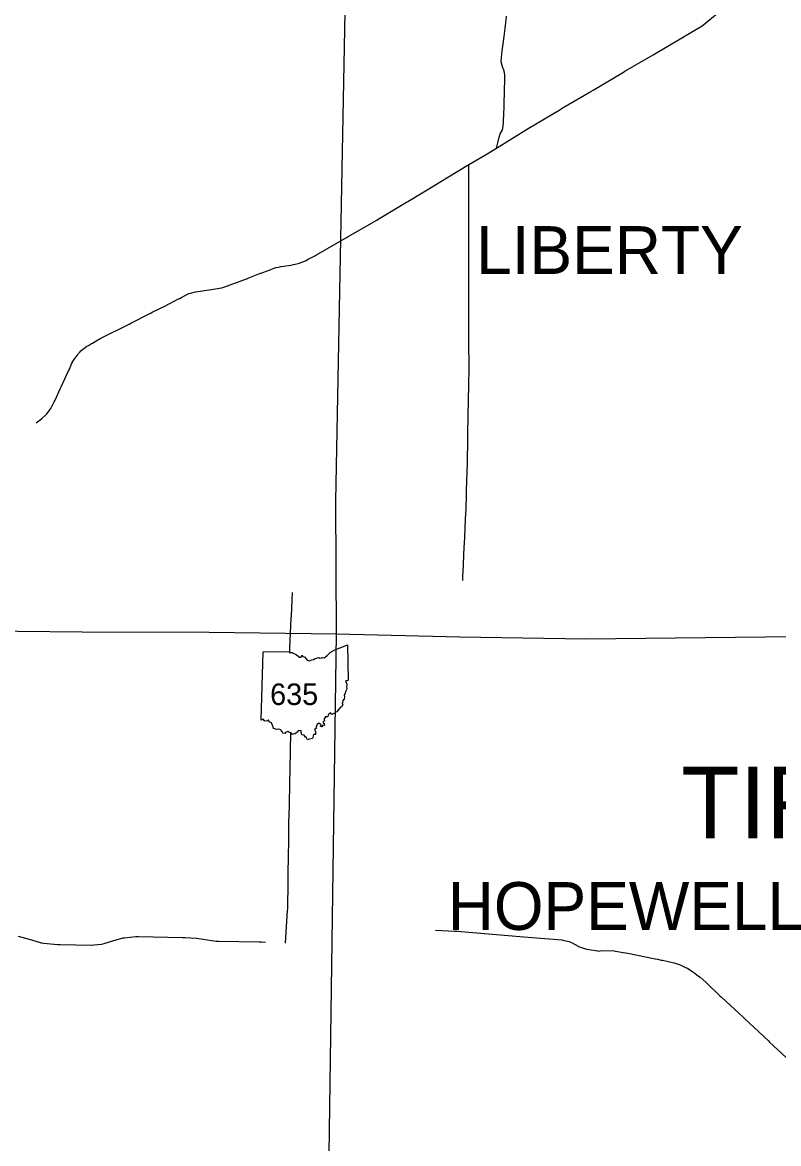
# Model space of a CAD drawing. Extents: x -232 to 448, y 619 to 1059.
# Drawn here: x 225.38 to 257.82, y 726.2 to 774.33 of the extents above; entities that cross this region are included whole.
import ezdxf

# ---------------------------------------------------------------- set-up
doc = ezdxf.new("R2010")
doc.units = 0
doc.layers.add('Default', color=7, linetype='Continuous')

msp = doc.modelspace()

# ---------------------------------------------------------------- linework, layer by layer
at = {"layer": 'Default'}
msp.add_line((235.625, 744.376), (235.707, 747.305), dxfattribs=at)
msp.add_line((235.625, 744.376), (235.707, 747.305), dxfattribs=at)
for points in [[(238.85, 748.082), (238.831, 753.779), (239.337, 780.795)], [(248.168, 770.427), (248.427, 770.582), (248.506, 770.629), (249.769, 771.367), (249.858, 771.419), (251.16, 772.198), (251.217, 772.232), (252.434, 772.942), (252.509, 772.986), (253.768, 773.731), (253.817, 773.76), (254.474, 774.14), (254.539, 774.177), (255.582, 775.042), (255.638, 775.087), (256.714, 775.996), (256.765, 776.038), (257.088, 776.311)], [(245.718, 768.939), (245.773, 769.158), (245.836, 769.407), (245.873, 769.554), (245.975, 769.713), (246.008, 769.882), (246.015, 770.067), (246.029, 770.419), (246.039, 770.672), (246.05, 770.975), (246.058, 771.228), (246.066, 771.513), (246.073, 771.782), (246.08, 772.07), (246.043, 772.254), (245.979, 772.43), (245.92, 772.644), (245.927, 772.821), (245.963, 773.108), (246, 773.41), (246.04, 773.731), (246.083, 774.068), (246.114, 774.317), (246.144, 774.603)], [(245.239, 768.653), (245.64, 768.892), (245.718, 768.939), (247.008, 769.736), (247.077, 769.779), (248.168, 770.427)], [(237.996, 764.352), (239.307, 765.116), (239.356, 765.144), (240.577, 765.847), (240.642, 765.885), (241.851, 766.608), (241.914, 766.646), (243.214, 767.427), (243.262, 767.456), (244.465, 768.189), (244.465, 768.189), (244.524, 768.225), (245.239, 768.653)], [(244.527, 764.31), (244.524, 765.662), (244.524, 765.728), (244.531, 766.758), (244.532, 766.853), (244.524, 768.153), (244.524, 768.153), (244.524, 768.225)], [(225.966, 757.137), (226.136, 757.264), (226.217, 757.325), (226.375, 757.473), (226.433, 757.528), (226.558, 757.705), (226.593, 757.754), (226.743, 758.043), (226.778, 758.11), (227.002, 758.603), (227.037, 758.68), (227.355, 759.368), (227.393, 759.449), (227.505, 759.696), (227.54, 759.774), (227.633, 759.908), (227.674, 759.967), (227.74, 760.053), (227.775, 760.099), (227.847, 760.18), (227.888, 760.227), (227.968, 760.299), (228.011, 760.338), (228.147, 760.427), (228.208, 760.467), (228.302, 760.522), (228.381, 760.568), (228.615, 760.705), (228.615, 760.705), (228.673, 760.739), (228.721, 760.763), (229.934, 761.365), (229.953, 761.374), (230.03, 761.414), (230.848, 761.838), (230.882, 761.855), (230.944, 761.886), (231.575, 762.199), (231.609, 762.215), (231.672, 762.248), (232.104, 762.473), (232.127, 762.485), (232.2, 762.523), (232.487, 762.675), (232.519, 762.693), (232.589, 762.71), (232.798, 762.765), (232.802, 762.766), (232.906, 762.78), (233.389, 762.844), (233.393, 762.845), (233.495, 762.863), (233.922, 762.937), (233.972, 762.946), (234.026, 762.965), (234.992, 763.321), (235.012, 763.328), (235.093, 763.36), (235.596, 763.559), (235.626, 763.571), (235.698, 763.598), (236.001, 763.713), (236.037, 763.727), (236.103, 763.75), (236.256, 763.804), (236.265, 763.807), (236.362, 763.828), (236.468, 763.852), (236.481, 763.855), (236.575, 763.866), (236.897, 763.907), (236.907, 763.908), (237.003, 763.932), (237.213, 763.984), (237.264, 763.997), (237.316, 764.017), (237.517, 764.098), (237.546, 764.11), (237.613, 764.146), (237.804, 764.249), (237.832, 764.264), (237.899, 764.3), (237.947, 764.326), (237.996, 764.352)], [(244.528, 763.223), (244.528, 763.929), (244.527, 764.31)], [(244.266, 750.367), (244.277, 750.61), (244.281, 750.702), (244.336, 751.838), (244.341, 751.938), (244.371, 752.587), (244.374, 752.648), (244.404, 753.297), (244.404, 753.297), (244.409, 753.388), (244.45, 754.796), (244.452, 754.879), (244.481, 756.287), (244.483, 756.364), (244.508, 757.718), (244.509, 757.816), (244.536, 759.062), (244.538, 759.167), (244.535, 760.955), (244.534, 761.06), (244.528, 762.36), (244.528, 762.431), (244.528, 763.223)], [(236.849, 747.323), (236.85, 747.361), (236.853, 747.466), (236.914, 748.765), (236.918, 748.848), (236.965, 749.851)], [(205.775, 748.382), (218.839, 748.24), (222.221, 748.221), (222.402, 748.227), (227.948, 748.176), (233.391, 748.153), (238.85, 748.082)], [(238.399, 715.587), (238.85, 748.082)], [(238.85, 748.082), (244.144, 747.953), (249.543, 747.875), (271.364, 748.108)], [(235.707, 747.305), (236.844, 747.324), (236.826, 747.289), (236.933, 747.282), (237.047, 747.219), (237.143, 747.179), (237.261, 747.086), (237.332, 747.087), (237.361, 747.164), (237.415, 747.105), (237.48, 747.094), (237.59, 746.954), (237.682, 746.924), (237.791, 746.972), (237.873, 746.98), (237.933, 747.027), (238.089, 747.068), (238.132, 747.043), (238.215, 747.048), (238.257, 747.066), (238.329, 747.05), (238.455, 747.157), (238.586, 747.282), (238.787, 747.401), (239.086, 747.513), (239.323, 747.613), (239.358, 746.094)], [(235.707, 747.305), (236.844, 747.324), (236.826, 747.289), (236.933, 747.282), (237.047, 747.219), (237.143, 747.179), (237.261, 747.086), (237.332, 747.087), (237.361, 747.164), (237.415, 747.105), (237.48, 747.094), (237.59, 746.954), (237.682, 746.924), (237.791, 746.972), (237.873, 746.98), (237.933, 747.027), (238.089, 747.068), (238.132, 747.043), (238.215, 747.048), (238.257, 747.066), (238.329, 747.05), (238.455, 747.157), (238.586, 747.282), (238.787, 747.401), (239.086, 747.513), (239.323, 747.613), (239.358, 746.094)], [(239.358, 746.094), (239.323, 746.072), (239.268, 746.082), (239.232, 746.04), (239.277, 745.968), (239.298, 745.893), (239.279, 745.811), (239.298, 745.742), (239.285, 745.685), (239.251, 745.628), (239.239, 745.574), (239.21, 745.517), (239.213, 745.485), (239.185, 745.459), (239.19, 745.364), (239.176, 745.312), (239.181, 745.266), (239.136, 745.254), (239.146, 745.217), (239.117, 745.188), (239.123, 745.138), (239.091, 745.106), (239.122, 745.042), (239.097, 745.022), (239.076, 744.944), (239.018, 744.929), (238.903, 744.787), (238.862, 744.733), (238.816, 744.72), (238.791, 744.665), (238.735, 744.665), (238.649, 744.626), (238.594, 744.692), (238.497, 744.613), (238.486, 744.522), (238.364, 744.525), (238.369, 744.478), (238.342, 744.465), (238.317, 744.419), (238.331, 744.337), (238.274, 744.316), (238.281, 744.268), (238.317, 744.239), (238.334, 744.148), (238.273, 744.166), (238.223, 744.089), (238.172, 744.107), (238.189, 744.172), (238.102, 744.251), (238.02, 744.188), (237.977, 744.088), (237.977, 744.02), (237.916, 743.979), (237.955, 743.884), (237.948, 743.819), (237.949, 743.756), (237.873, 743.759), (237.827, 743.59)], [(239.358, 746.094), (239.323, 746.072), (239.268, 746.082), (239.232, 746.04), (239.277, 745.968), (239.298, 745.893), (239.279, 745.811), (239.298, 745.742), (239.285, 745.685), (239.251, 745.628), (239.239, 745.574), (239.21, 745.517), (239.213, 745.485), (239.185, 745.459), (239.19, 745.364), (239.176, 745.312), (239.181, 745.266), (239.136, 745.254), (239.146, 745.217), (239.117, 745.188), (239.123, 745.138), (239.091, 745.106), (239.122, 745.042), (239.097, 745.022), (239.076, 744.944), (239.018, 744.929), (238.903, 744.787), (238.862, 744.733), (238.816, 744.72), (238.791, 744.665), (238.735, 744.665), (238.649, 744.626), (238.594, 744.692), (238.497, 744.613), (238.486, 744.522), (238.364, 744.525), (238.369, 744.478), (238.342, 744.465), (238.317, 744.419), (238.331, 744.337), (238.274, 744.316), (238.281, 744.268), (238.317, 744.239), (238.334, 744.148), (238.273, 744.166), (238.223, 744.089), (238.172, 744.107), (238.189, 744.172), (238.102, 744.251), (238.02, 744.188), (237.977, 744.088), (237.977, 744.02), (237.916, 743.979), (237.955, 743.884), (237.948, 743.819), (237.949, 743.756), (237.873, 743.759), (237.827, 743.59)], [(237.827, 743.59), (237.694, 743.558), (237.602, 743.539), (237.569, 743.615), (237.504, 743.656), (237.461, 743.733), (237.366, 743.743), (237.344, 743.849), (237.333, 743.934), (237.204, 743.913), (237.169, 743.861), (237.123, 743.847), (237.096, 743.794), (237.034, 743.789), (236.967, 743.765), (236.923, 743.816), (236.813, 743.868), (236.763, 743.895), (236.66, 743.854), (236.638, 743.804), (236.556, 743.826), (236.537, 743.881), (236.487, 743.897), (236.476, 743.956), (236.37, 743.987), (236.288, 743.975), (236.145, 744.021), (236.136, 744.098), (236.087, 744.192), (236.062, 744.257), (235.971, 744.306), (235.953, 744.383), (235.924, 744.381), (235.897, 744.35), (235.796, 744.335), (235.756, 744.367), (235.7, 744.421), (235.625, 744.376)], [(237.827, 743.59), (237.694, 743.558), (237.602, 743.539), (237.569, 743.615), (237.504, 743.656), (237.461, 743.733), (237.366, 743.743), (237.344, 743.849), (237.333, 743.934), (237.204, 743.913), (237.169, 743.861), (237.123, 743.847), (237.096, 743.794), (237.034, 743.789), (236.967, 743.765), (236.923, 743.816), (236.813, 743.868), (236.763, 743.895), (236.66, 743.854), (236.638, 743.804), (236.556, 743.826), (236.537, 743.881), (236.487, 743.897), (236.476, 743.956), (236.37, 743.987), (236.288, 743.975), (236.145, 744.021), (236.136, 744.098), (236.087, 744.192), (236.062, 744.257), (235.971, 744.306), (235.953, 744.383), (235.924, 744.381), (235.897, 744.35), (235.796, 744.335), (235.756, 744.367), (235.7, 744.421), (235.625, 744.376)], [(236.668, 734.801), (236.754, 736.207), (236.758, 736.267), (236.778, 737.459), (236.779, 737.514), (236.799, 738.814), (236.801, 738.92), (236.815, 740.112), (236.816, 740.192), (236.848, 741.546), (236.85, 741.648), (236.876, 743.002), (236.877, 743.069), (236.899, 743.827)], [(225.191, 735.103), (225.662, 734.975), (225.662, 734.975), (225.717, 734.959), (225.769, 734.944), (226.186, 734.826), (226.21, 734.819), (226.292, 734.811), (226.884, 734.751), (226.924, 734.747), (226.992, 734.745), (228.344, 734.723), (228.372, 734.723), (228.451, 734.731), (228.774, 734.765), (228.827, 734.77), (228.879, 734.786), (229.345, 734.928), (229.375, 734.937), (229.449, 734.958), (229.657, 735.018), (229.695, 735.029), (229.763, 735.037), (230.246, 735.092), (230.283, 735.096), (230.354, 735.094), (232.246, 735.046), (232.27, 735.046), (232.354, 735.042), (232.84, 735.024), (232.864, 735.023), (232.947, 735.01), (233.696, 734.897), (233.721, 734.893), (233.804, 734.892), (235.534, 734.868), (235.586, 734.867), (235.642, 734.863), (235.804, 734.853)], [(243.105, 735.37), (243.915, 735.321), (243.969, 735.318), (244.023, 735.313), (246.89, 735.078)], [(246.89, 735.078), (248.514, 734.944), (248.566, 734.94), (248.619, 734.926), (248.83, 734.871), (248.86, 734.863), (248.929, 734.828), (249.218, 734.679), (249.239, 734.668), (249.319, 734.64), (249.576, 734.552), (249.598, 734.545), (249.682, 734.532), (250.058, 734.474), (250.096, 734.468), (250.166, 734.471), (250.708, 734.487), (250.711, 734.487), (250.815, 734.468), (251.242, 734.39), (251.255, 734.388), (251.349, 734.369), (252.519, 734.133), (252.54, 734.129), (252.626, 734.112), (252.786, 734.08), (252.839, 734.069)], [(252.839, 734.069), (253.263, 733.978), (253.344, 733.96), (253.547, 733.885), (253.628, 733.855), (253.825, 733.765), (253.912, 733.725), (254.093, 733.607), (254.167, 733.559), (254.383, 733.395), (254.453, 733.343), (254.696, 733.127), (254.757, 733.073), (255.304, 732.548), (255.304, 732.548), (255.372, 732.483), (256.13, 731.786)], [(256.13, 731.786), (256.289, 731.639), (256.357, 731.576), (257.381, 730.609), (257.431, 730.562), (258.502, 729.565), (258.576, 729.496), (259.824, 728.372), (259.867, 728.333), (260.784, 727.489), (260.85, 727.428), (261.306, 727.028)]]:
    msp.add_lwpolyline(points, dxfattribs=at)

# ---------------------------------------------------------------- texts
for s, height, p in [('LIBERTY', 2.052, (244.844, 763.532)), ('635', 0.9234, (236.006, 745.029)), ('TIFFIN', 3.078, (253.632, 739.307)), ('HOPEWELL', 2.052, (243.62, 735.373))]:
    msp.add_text(s, height=height, dxfattribs=at).set_placement(p)

doc.saveas('drawing.dxf')
